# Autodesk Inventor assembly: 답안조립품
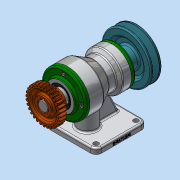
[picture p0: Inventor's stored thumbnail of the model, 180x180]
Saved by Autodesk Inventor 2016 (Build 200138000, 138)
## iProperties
Created: 2019-01
Part Number: 답안조립품
Document SubType Name: Assembly
Designer: MIRAE
Author: MIRAE
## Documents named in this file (15)
- C:\Users\MIRAE\Desktop\490107V1038\답안조립품.iam
- C:\Users\MIRAE\Desktop\490107V1038\본체.ipt
- C:\Users\MIRAE\Desktop\490107V1038\축.ipt
- C:\Users\MIRAE\Desktop\490107V1038\키 6 x 6 x 18.ipt
- C:\Users\MIRAE\Desktop\490107V1038\키 5 x 5 x 20.ipt
- C:\Users\MIRAE\Desktop\490107V1038\베어링 6205.ipt
- C:\Users\MIRAE\Desktop\490107V1038\베어링 6203.ipt
- C:\Users\MIRAE\Desktop\490107V1038\뒤커버.ipt
- C:\Users\MIRAE\Desktop\490107V1038\앞커버.ipt
- C:\Users\MIRAE\Desktop\490107V1038\오일 실 25 38 8.ipt
- C:\Users\MIRAE\Desktop\490107V1038\오일 실 17 30 8.ipt
- C:\Users\MIRAE\Desktop\490107V1038\스퍼기어.ipt
- C:\Users\MIRAE\Desktop\490107V1038\V-벨트풀리.ipt
- C:\Users\MIRAE\Desktop\490107V1038\멈춤나사 M3.ipt
- C:\Users\MIRAE\Desktop\490107V1038\볼트 M4.ipt
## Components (1 placed, 1 different names)
1. V-벨트풀리:1
